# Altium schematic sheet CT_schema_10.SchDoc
size 278 x 170 mm
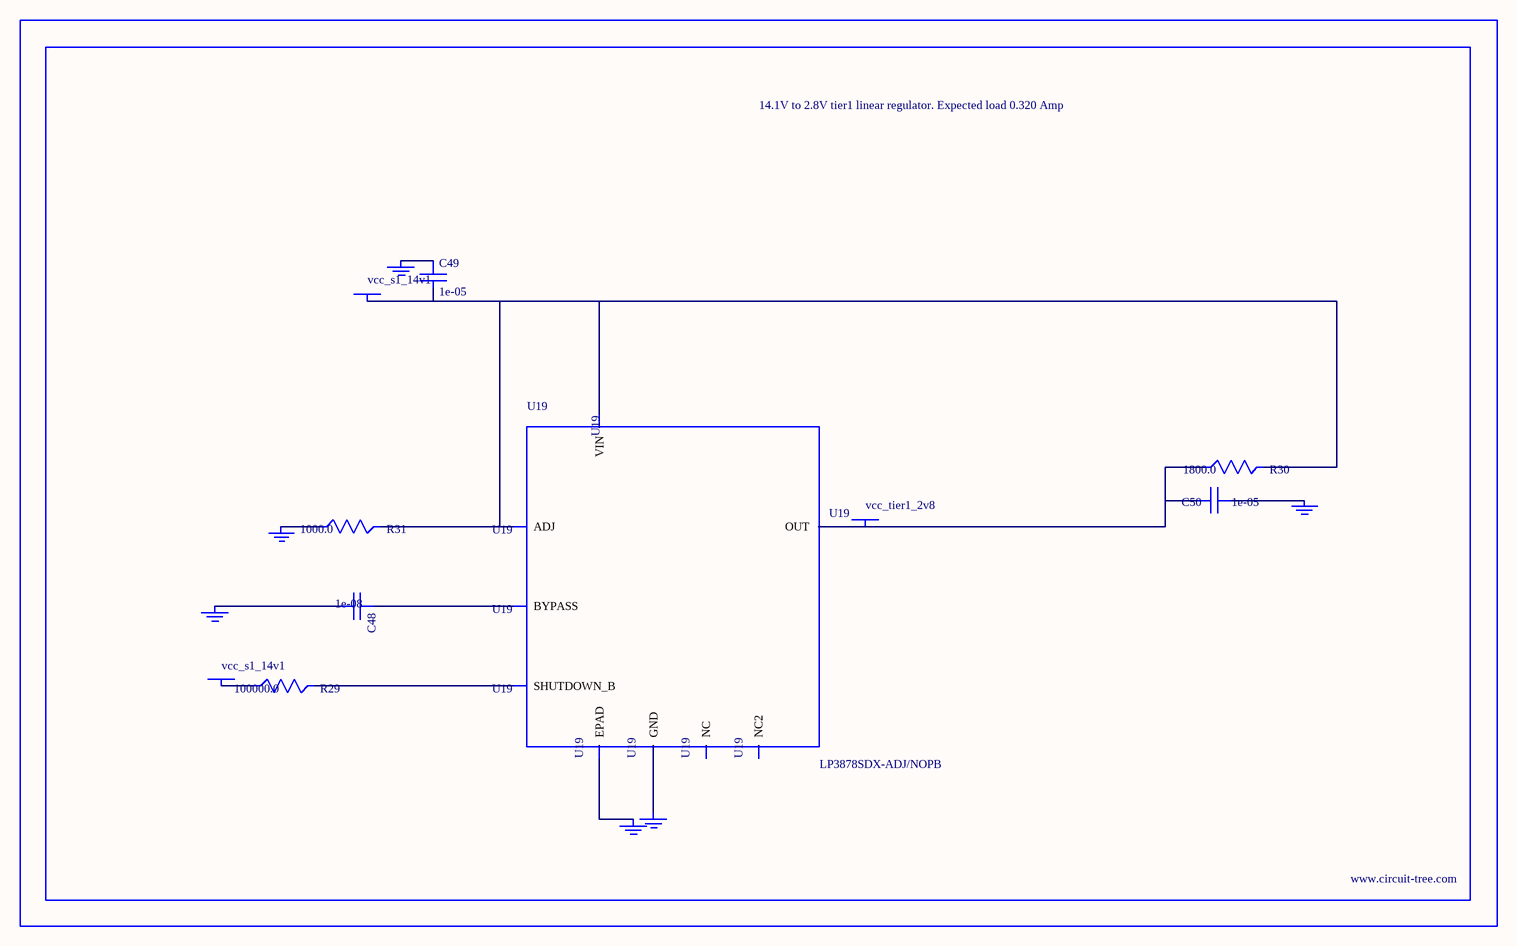
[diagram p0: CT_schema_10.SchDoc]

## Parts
BORDER9  (no value)
C48  1e-08  [C0402]
C49  1e-05  [C1210]
C50  1e-05  [C1210]
GND_INSTANCE_9_0  (no value)
GND_INSTANCE_9_1  (no value)
GND_INSTANCE_9_2  (no value)
GND_INSTANCE_9_3  (no value)
GND_INSTANCE_9_4  (no value)
GND_INSTANCE_9_5  (no value)
POWER_INSTANCE_9_0  vcc_s1_14v1
POWER_INSTANCE_9_1  vcc_s1_14v1
POWER_INSTANCE_9_2  vcc_tier1_2v8
R29  100000.0  [R0603]
R30  1800.0  [R0603]
R31  1000.0  [R0603]
U19  LP3878SDX-ADJ/NOPB  [WSON-8]

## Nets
NetC48_1: C48.1 U19.1(BYPASS)
NetC48_2: C48.2 GND_INSTANCE_9_0.0(GND)
NetC49_1: C49.1 GND_INSTANCE_9_1.0(GND)
NetC49_2: C49.2 POWER_INSTANCE_9_0.0(PWR) R30.2 R31.2 U19.4(VIN) U19.6(ADJ)
NetC50_1: C50.1 GND_INSTANCE_9_2.0(GND)
NetC50_2: C50.2 POWER_INSTANCE_9_2.0(PWR) R30.1 U19.5(OUT)
NetGND_INSTANCE_9_3_0: GND_INSTANCE_9_3.0(GND) R31.1
NetGND_INSTANCE_9_4_0: GND_INSTANCE_9_4.0(GND) U19.PAD(EPAD)
NetGND_INSTANCE_9_5_0: GND_INSTANCE_9_5.0(GND) U19.3(GND)
NetPOWER_INSTANCE_9_1_0: POWER_INSTANCE_9_1.0(PWR) R29.1
NetR29_2: R29.2 U19.8(SHUTDOWN_B)

Not connected (* = marked no-connect by the designer): U19 2(NC) 7(NC2)

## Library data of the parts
BORDER9 = BORDER_PAGE9
C48 = C0402C103K3RAC
C49 = C1210C106K5PACTU
C50 = GRM32DR61E106MA12L
GND_INSTANCE_9_0-GND_INSTANCE_9_5 = GND
POWER_INSTANCE_9_0-POWER_INSTANCE_9_2 = PWR
R29 = RC0603JR-07100KL
R30 = RC0603JR-071K8L
R31 = RC0603JR-071KL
